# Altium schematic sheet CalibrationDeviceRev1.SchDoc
size A2; SheetNumber: 1; SheetTotal: 1; SPICEModelCacheJMJTSHEM: <root> / <DocumentId>JMJTSHEM</DocumentId> / </root>
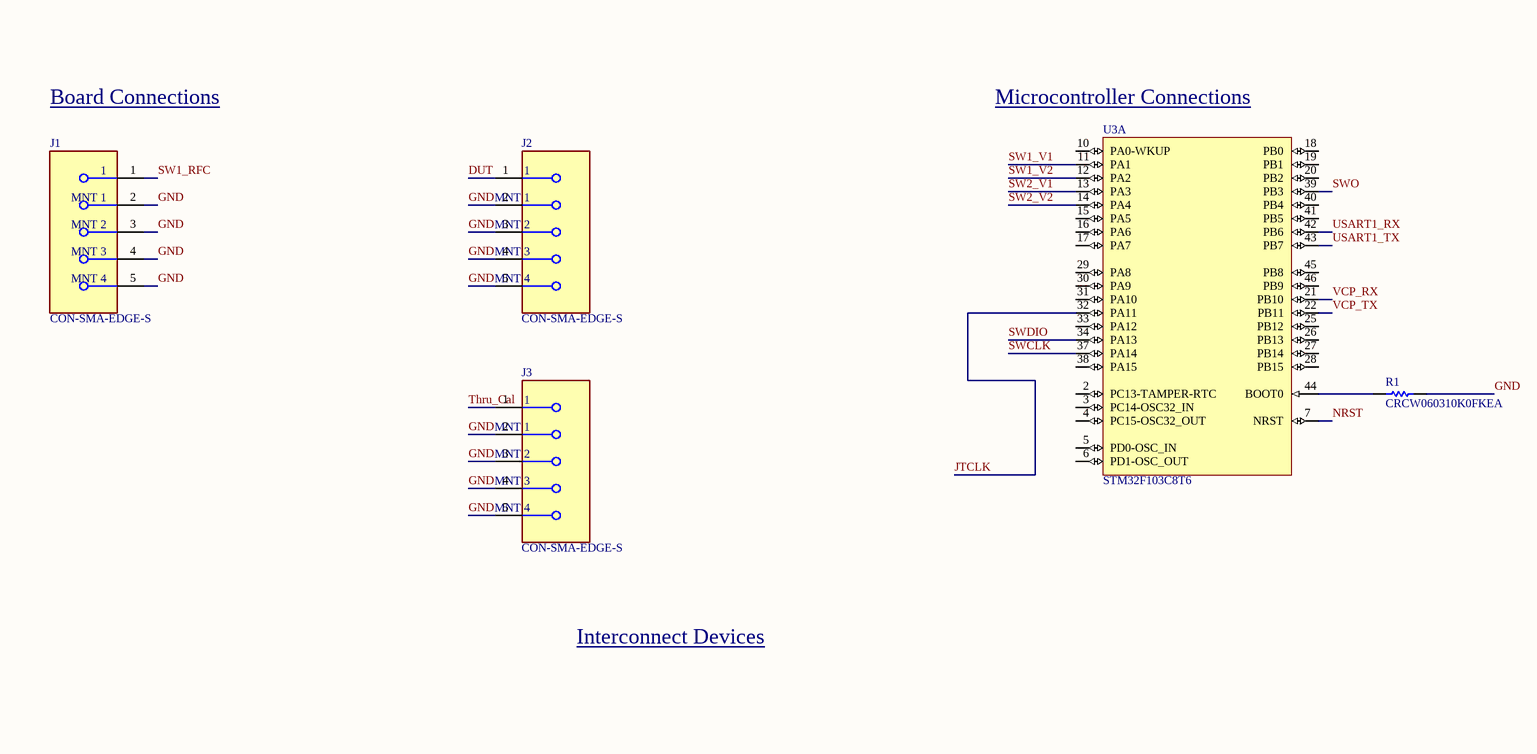
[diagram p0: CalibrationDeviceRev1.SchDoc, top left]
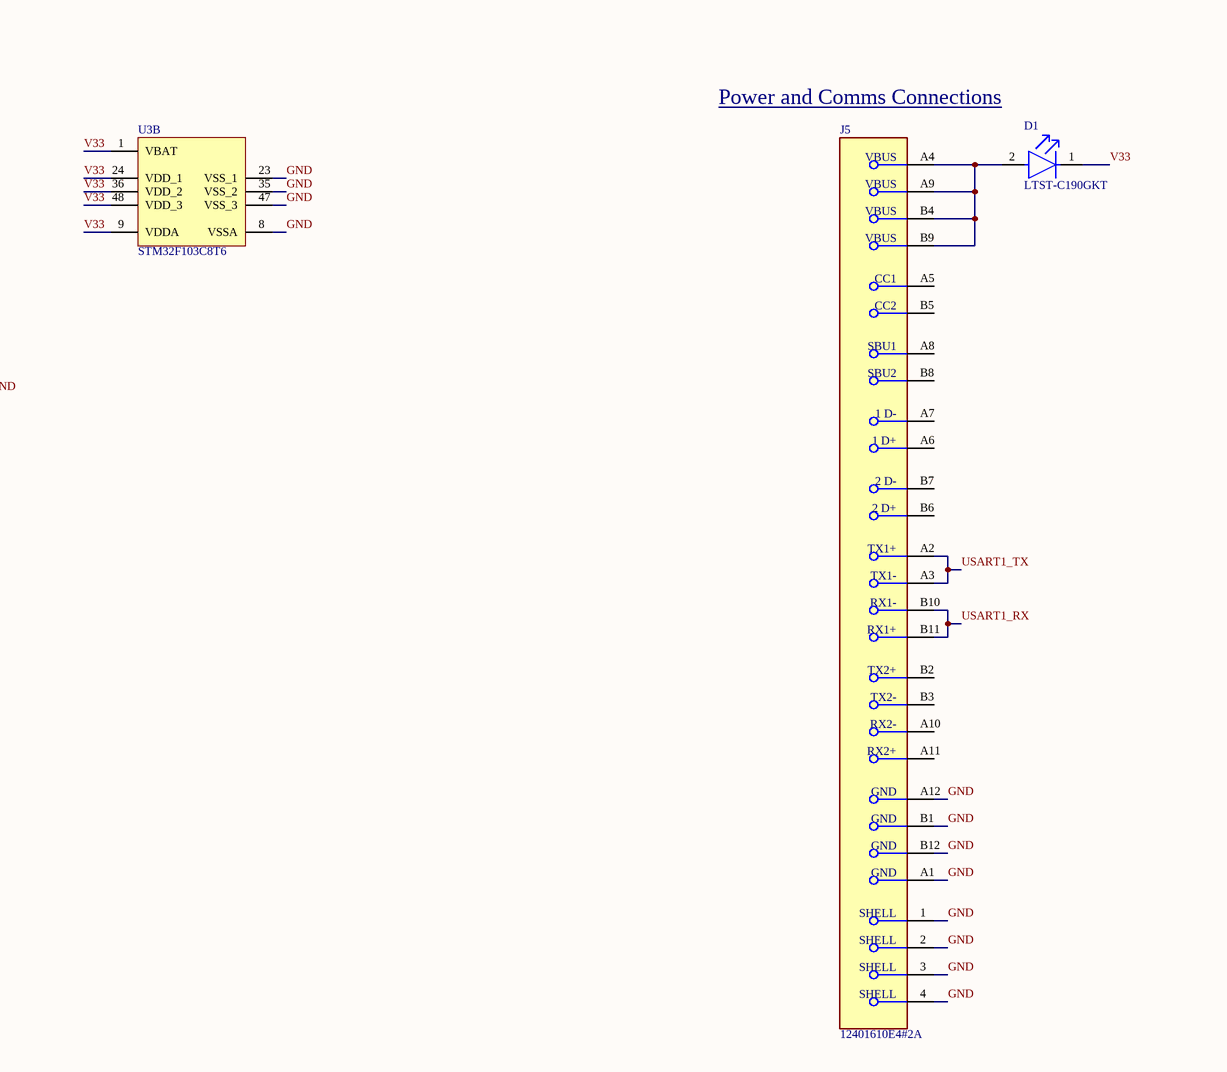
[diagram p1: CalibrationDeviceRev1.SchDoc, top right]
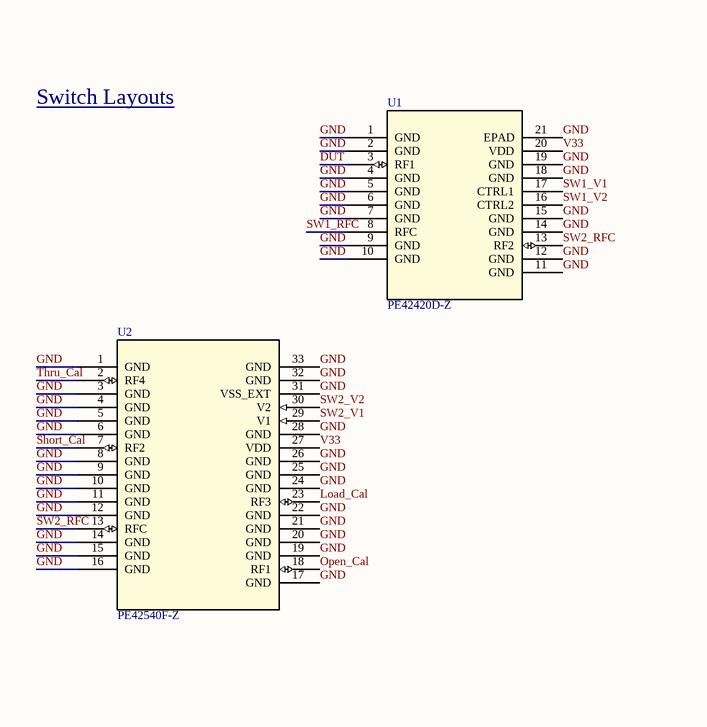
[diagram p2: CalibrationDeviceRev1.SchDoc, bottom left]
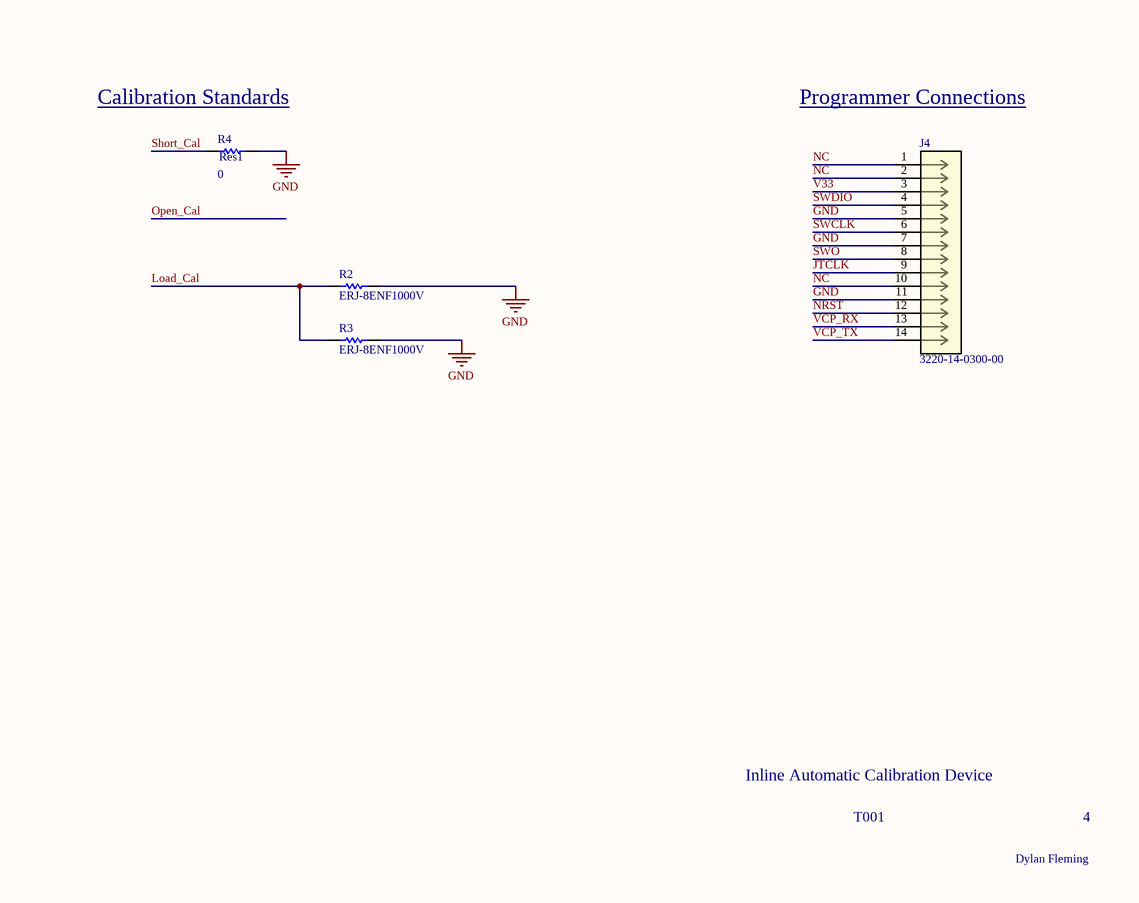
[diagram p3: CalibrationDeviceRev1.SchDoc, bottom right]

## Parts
D1  LTST-C190GKT  [FP-LTST-C190GKT-MFG]
J1  CON-SMA-EDGE-S  [FP-CON-SMA-EDGE-S-MFG]
J2  CON-SMA-EDGE-S  [FP-CON-SMA-EDGE-S-MFG]
J3  CON-SMA-EDGE-S  [FP-CON-SMA-EDGE-S-MFG]
J4  3220-14-0300-00  [CONN_3220-14-0300-00_CNC]
J5  12401610E4#2A  [FP-12401610E4#2A-MFG]
R1  CRCW060310K0FKEA  [RESC1609X50X30LL8T20]
R2  ERJ-8ENF1000V  [RESC3216X70X50NL05T20]
R3  ERJ-8ENF1000V  [RESC3216X70X50NL05T20]
R4  Res1  value 0  [AXIAL-0.3]
U1  PE42420D-Z  [LGA20_4X4_PSM]
U2  PE42540F-Z  [PE42540G-Z]
U3  STM32F103C8T6  [STM-LQFP48_L]  (parts A,B of 2)

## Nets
GND: J1.2(MNT_1) J1.3(MNT_2) J1.4(MNT_3) J1.5(MNT_4) J2.2(MNT_1) J2.3(MNT_2) J2.4(MNT_3) J2.5(MNT_4) J3.2(MNT_1) J3.3(MNT_2) J3.4(MNT_3) J3.5(MNT_4) J4.5 J4.7 J4.11 J5.1(SHELL) J5.2(SHELL) J5.3(SHELL) J5.4(SHELL) J5.A1(GND) J5.A12(GND) J5.B1(GND) J5.B12(GND) R1.2 R2.2 R3.2 R4.2 U1.1(GND) U1.2(GND) U1.4(GND) U1.5(GND) U1.6(GND) U1.7(GND) U1.9(GND) U1.10(GND) U1.11(GND) U1.12(GND) U1.14(GND) U1.15(GND) U1.18(GND) U1.19(GND) U1.21(EPAD) U2.1(GND) U2.3(GND) U2.4(GND) U2.5(GND) U2.6(GND) U2.8(GND) U2.9(GND) U2.10(GND) U2.11(GND) U2.12(GND) U2.14(GND) U2.15(GND) U2.16(GND) U2.17(GND) U2.19(GND) U2.20(GND) U2.21(GND) U2.22(GND) U2.24(GND) U2.25(GND) U2.26(GND) U2.28(GND) U2.31(VSS_EXT) U2.32(GND) U2.33(GND) U3.8(VSSA) U3.23(VSS_1) U3.35(VSS_2) U3.47(VSS_3)
DUT: J2.1 U1.3(RF1)
JTCLK: J4.9 U3.32(PA11)
Load_Cal: R2.1 R3.1 U2.23(RF3)
NC: J4.1 J4.2 J4.10
NRST: J4.12 U3.7(NRST)
Open_Cal: U2.18(RF1)
Short_Cal: R4.1 U2.7(RF2)
SW1_RFC: J1.1 U1.8(RFC)
SW1_V1: U1.17(CTRL1) U3.11(PA1)
SW1_V2: U1.16(CTRL2) U3.12(PA2)
SW2_RFC: U1.13(RF2) U2.13(RFC)
SW2_V1: U2.29(V1) U3.13(PA3)
SW2_V2: U2.30(V2) U3.14(PA4)
SWCLK: J4.6 U3.37(PA14)
SWDIO: J4.4 U3.34(PA13)
SWO: J4.8 U3.39(PB3)
Thru_Cal: J3.1 U2.2(RF4)
USART1_RX: J5.B10(RX1-) J5.B11(RX1+) U3.42(PB6)
USART1_TX: J5.A2(TX1+) J5.A3(TX1-) U3.43(PB7)
V33: D1.1(C) J4.3 U1.20(VDD) U2.27(VDD) U3.1(VBAT) U3.9(VDDA) U3.24(VDD_1) U3.36(VDD_2) U3.48(VDD_3)
VCP_RX: J4.13 U3.21(PB10)
VCP_TX: J4.14 U3.22(PB11)
NetD1_2: D1.2(A) J5.A4(VBUS) J5.A9(VBUS) J5.B4(VBUS) J5.B9(VBUS)
NetR1_1: R1.1 U3.44(BOOT0)

Not connected (* = marked no-connect by the designer): J5 A5(CC1) A6(1_D+) A7(1_D-) A8(SBU1) A10(RX2-) A11(RX2+) B2(TX2+) B3(TX2-) B5(CC2) B6(2_D+) B7(2_D-) B8(SBU2); U3 2(PC13-TAMPER-RTC) 3(PC14-OSC32_IN) 4(PC15-OSC32_OUT) 5(PD0-OSC_IN) 6(PD1-OSC_OUT) 10(PA0-WKUP) 15(PA5) 16(PA6) 17(PA7) 18(PB0) 19(PB1) 20(PB2) 25(PB12) 26(PB13) 27(PB14) 28(PB15) 29(PA8) 30(PA9) 31(PA10) 33(PA12) 38(PA15) 40(PB4) 41(PB5) 45(PB8) 46(PB9)

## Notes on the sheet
- Board Connections
- (near U3) Microcontroller Connections
- Power and Comms Connections
- Interconnect Devices
- Switch Layouts
- (near R4) Calibration Standards
- Programmer Connections
- Inline Automatic Calibration Device
- T001
- Dylan Fleming
- 4

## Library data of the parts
D1 = CMP-22017-000005-2: LED GREEN CLEAR CHIP SMD; Dominant Wavelength: 569nm; Reverse Voltage: 5V; Lens Color: Colorless; Viewing Angle: 130°; Voltage: 2V; Forward Current: 30mA; Power Dissipation: 100mW; Luminous Intensity: 6mcd; Number of LEDs: 1; Forward Voltage: 2.1V; Wavelength: 565nm; Test Current: 10mA
J1-J3 = CMP-204357-000001-1: CONN SMA JACK STR EDGE MNT; Manufacturer: RF Solutions Ltd.; Impedance: 50Ω; Conn Orientation: Right Angle; Is Female: yes; Number Of Contacts: 1; Frequency: 18GHz; Shielding: true
J4 = 3220-14-0300-00: No Description Available; Mfr_Name: CNC Tech
J5 = CMP-15126-126516878-1: 12401610E4#2A Conn USB Type C RCP 24 POS 0.5mm Solder RA SMD 24 Terminal 1 Port Automotive; Gender: Receptacle; USB Standard: USB 3.1; Number of Contacts: 24; Current Rating: 5A
R1 = CMP-1666-00005-4: Chip Resistor, 10 KOhm, +/- 1%, 100 mW, -55 to 155 degC, 0603 (1608 Metric), RoHS, Tape and Reel; Manufacturer: Vishay Semiconductor; Voltage Rating: 75 V
R2 R3 = CMP-2003-00016-1: Manufacturer: Panasonic
R4 = Res1: Resistor
U1 = PE42420D-Z: No Description Available; Mfr_Name: pSemi
U2 = PE42540F-Z: No Description Available; Mfr_Name: Peregine Semiconductor
U3 = CMP-0237-00215-3: ARM Cortex-M3 32-bit MCU, 64 KB Flash, 20 KB Internal RAM, 37 I/Os, 48-pin LQFP, -40 to 85 degC, Tray; Supply Voltage(Vcc) min (V): 2; Internal RAM Size (kB): 20; FLASH Size (Prog) (kB): 64; A/D Converter: 2x12-bit (10 Channel); I/Os (High Current): 37; Operating Frequency(F) (Processor speed) (MHz): 72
